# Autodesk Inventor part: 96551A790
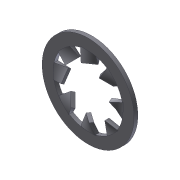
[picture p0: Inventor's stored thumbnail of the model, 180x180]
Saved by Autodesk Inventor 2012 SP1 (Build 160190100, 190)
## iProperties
Created: 2012-03
Part Number: 96551A790
Material: Stainless Steel
Document SubType Name: Modeling
Designer: jdh
Density: 8.08 g/cm^3
Mass: 0.278246 g
Surface Area: 1.821 cm^2
Volume: 0.0344364 cm^3
Translation Standard: STEP AP203
FileName: 96551A790.step
PreProcessor: SolidWorks 2007
PostProcessor: Build: 190, Release: 2012 SP1 - Date: Mon 08/08/2011
Sent Units: inch
Uncertainty: 1e-05
Author: jdh
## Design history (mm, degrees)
node "96551A7901"
node "NONE"
node "Base1"
